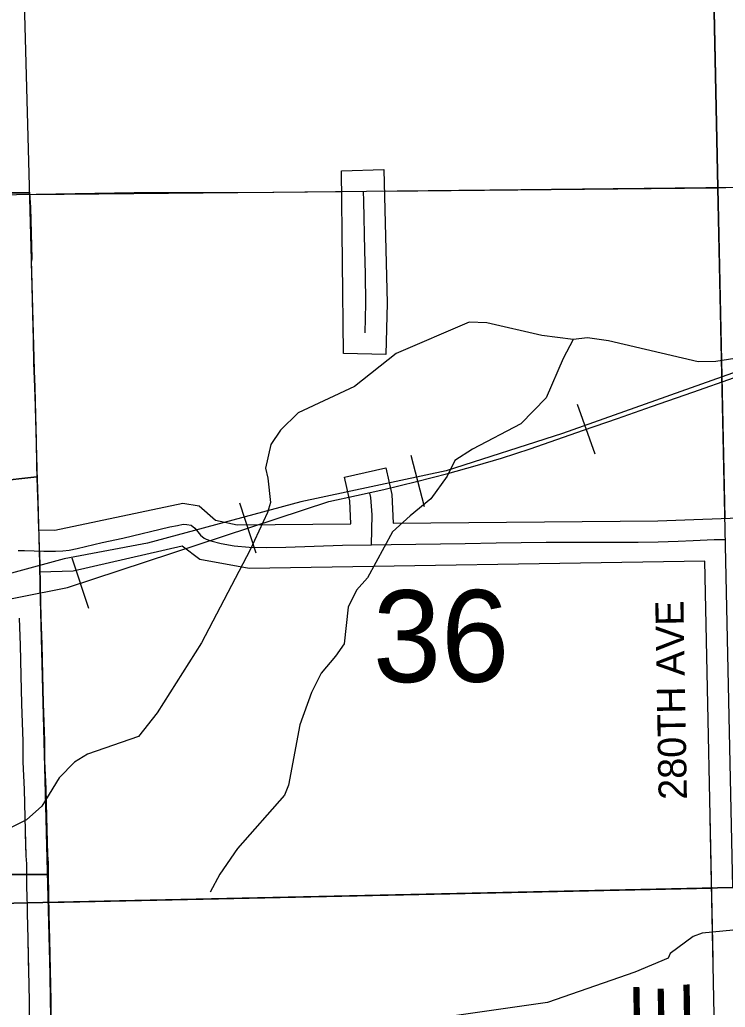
# Model space of a CAD drawing. Extents: x 10133 to 81668, y 7924 to 11018.
# Drawn here: x 11135.9 to 11285.8, y 9007.3 to 9217.2 of the extents above; entities that cross this region are included whole.
import ezdxf

# ---------------------------------------------------------------- set-up
doc = ezdxf.new("R2010")
doc.units = 0
for name, color, linetype in [('tdCoCityStreetMajor', 7, 'Continuous'), ('tdCoCityStreetMinor', 7, 'Continuous'), ('tdCoHydroRiver', 7, 'Continuous'), ('tdCoPriNonDiv', 7, 'Continuous'), ('tdCoRRCL', 7, 'Continuous'), ('tdCoRROwnerTxt', 7, 'Continuous'), ('tdCoSecRteBand', 7, 'Continuous'), ('tdCoShieldCoRteHrd', 7, 'Continuous'), ('tdCoShieldStRte', 7, 'Continuous'), ('tdCoStrucNonDivPri', 7, 'Continuous'), ('tdCoStrucSec', 7, 'Continuous'), ('tdCoSurfAsphalt', 7, 'Continuous'), ('tdCoSurfGravelUnbanded', 7, 'Continuous'), ('tdCoTwpNameTxt', 7, 'Continuous')]:
    doc.layers.add(name, color=color, linetype=linetype)

msp = doc.modelspace()

# ---------------------------------------------------------------- linework, layer by layer
at = {"layer": 'tdCoCityStreetMajor'}
for points in [[(11209.3, 9150.6), (11209.45, 9156.86), (11209.35, 9163.2), (11209.23, 9168.16), (11209.01, 9178.62), (11208.93, 9180.74)], [(11210.62, 9105.59), (11210.77, 9111.95), (11210.5, 9115.6), (11210.27, 9116.58)]]:
    msp.add_lwpolyline(points, dxfattribs=at)
at = {"layer": 'tdCoCityStreetMinor'}
msp.add_lwpolyline([(11135.49, 9104.34), (11136.86, 9104.35), (11140.98, 9104.2), (11143.44, 9104.2), (11145.05, 9104.3), (11146.33, 9104.4), (11148.05, 9104.75), (11153.36, 9106.03), (11157.75, 9107.01), (11167.78, 9109.38), (11169.36, 9109.7), (11170.62, 9109.92), (11171.41, 9109.87), (11172.27, 9109.73), (11173.09, 9109.13), (11173.73, 9108.3), (11174.29, 9107.63), (11175.06, 9106.99), (11175.5, 9106.74), (11176.51, 9106.42), (11178.68, 9105.86), (11181.47, 9105.36), (11184.65, 9105.04), (11188.38, 9105.02), (11192.42, 9105.09), (11204.48, 9105.49), (11210.62, 9105.59), (11214.84, 9105.66), (11230.54, 9105.86), (11237.15, 9106), (11247.78, 9106.15), (11255.58, 9106.15), (11267.34, 9106.15), (11271.58, 9106.18), (11275.82, 9106.32), (11279, 9106.5), (11283.47, 9106.67), (11285.91, 9106.73)], dxfattribs=at)
at = {"layer": 'tdCoHydroRiver'}
for points in [[(11253.47, 9149.25), (11246.83, 9150.09), (11235.18, 9152.73), (11231.39, 9152.91), (11215.87, 9146.25), (11206.99, 9139.24), (11195.01, 9133.59), (11191.28, 9129.97), (11189.2, 9126.86), (11188.1, 9121.87), (11188.61, 9119.75), (11189.17, 9114.55), (11188.5, 9112.4), (11184.84, 9104.53), (11174.52, 9084.7), (11165.06, 9069.86), (11161.12, 9064.82), (11150.29, 9061.09), (11147.47, 9059.38), (11144.22, 9056.01), (11140.53, 9050.03), (11137.26, 9047.13), (11129.51, 9043.22)], [(11292.36, 9145.88), (11283.86, 9144.55), (11280.07, 9144.49), (11261.05, 9148.9), (11256.54, 9149.54), (11253.47, 9149.25)], [(11253.47, 9149.25), (11251.41, 9145.19), (11247.76, 9136.84), (11242.41, 9131.31), (11232.08, 9125.92), (11228.33, 9123.49), (11226.73, 9120.15), (11223.26, 9115.36), (11218.82, 9111.73), (11215.09, 9108.35), (11209.8, 9098.55), (11207.48, 9095.91), (11205.65, 9092.33), (11204.83, 9084.5), (11202.98, 9081.86), (11199.96, 9078.26), (11197.9, 9074.2), (11195.41, 9067.29), (11193.02, 9054.46), (11192.11, 9052.32), (11182.12, 9041.02), (11178.42, 9035.51), (11176.35, 9031.69)], [(11344.52, 9029.3), (11332.9, 9030.29), (11329.6, 9029.53), (11322.5, 9029.17), (11318.94, 9029.58), (11313.04, 9028.3), (11292.23, 9026.77), (11287.55, 9023.61), (11280.93, 9023.02), (11279.04, 9022.28), (11274.13, 9018.65), (11274.05, 9018.47)], [(11287.54, 9023.61), (11280.92, 9023.02), (11279.04, 9022.28), (11274.13, 9018.65), (11273.67, 9017.69), (11266.62, 9014.73), (11248.02, 9008.26), (11227.7, 9005.32)]]:
    msp.add_lwpolyline(points, dxfattribs=at)
at = {"layer": 'tdCoPriNonDiv'}
for points in [[(11136.39, 9236.77), (11139.85, 9108.74), (11143.3, 9108.7)], [(11143.3, 9108.7), (11170.54, 9114.42), (11174.02, 9113.87), (11177.47, 9110.84), (11182.09, 9109.82), (11206.22, 9110.01), (11206.03, 9114.93), (11204.9, 9119.98), (11213.68, 9121.96), (11214.95, 9116.26), (11215.23, 9110.16), (11271.49, 9110.67), (11444.23, 9117.01), (11445.46, 9211.77), (11445.79, 9217.23)], [(11213.69, 9146), (11204.7, 9146.21), (11204.28, 9185.07), (11213.27, 9185.39), (11213.95, 9156.93), (11213.69, 9146)], [(11283.23, 9017.59), (11281.5, 9102.09), (11184.62, 9100.54), (11174.14, 9102.45), (11170.36, 9105.31), (11147.21, 9099.99), (11140.11, 9099.73), (11140.14, 9096.7), (11142.28, 9014.33)], [(11144.18, 8888.05), (11285.56, 8897.14), (11285.05, 8928.68), (11282.62, 9047.57)], [(11141.5, 9044.31), (11142.42, 9008.73), (11144.18, 8888.05)]]:
    msp.add_lwpolyline(points, dxfattribs=at)
at = {"layer": 'tdCoRRCL'}
for p, q in [((11258.16, 9124.81), (11254.45, 9135.43)), ((11221.88, 9113.64), (11219.09, 9124.54)), ((11186.14, 9103.77), (11182.62, 9114.45)), ((11150.52, 9092.04), (11147, 9102.72))]:
    msp.add_line(p, q, dxfattribs=at)
for points in [[(11383.11, 9177.72), (11374.43, 9174.35), (11360.55, 9167.76), (11338.88, 9160.33), (11251.25, 9129.22), (11226.5, 9121.28), (11195.58, 9114.67), (11163.03, 9105.91), (11145.32, 9102.57), (11125.98, 9097.32), (11109.94, 9093.06), (11085.46, 9083.46), (11066.85, 9076.56), (10954.88, 9032.59)], [(11124.89, 9092.32), (11146.01, 9096.47), (11201.59, 9114.78), (11207.43, 9116.04), (11213.27, 9117.29), (11216.75, 9118.16), (11220.23, 9119.02), (11226.83, 9120.72), (11232.65, 9122.37), (11238.24, 9123.98), (11244.33, 9125.98), (11250.03, 9127.95), (11255.73, 9129.92), (11262.93, 9132.43), (11270.13, 9134.95), (11278.95, 9138.04), (11287.78, 9141.12)]]:
    msp.add_lwpolyline(points, dxfattribs=at)
at = {"layer": 'tdCoSecRteBand'}
for points in [[(11137.81, 9014.23), (11137.67, 9021.57), (11137.59, 9024.74), (11137.54, 9026.95), (11137.5, 9028.68), (11137.44, 9030.79), (11137.37, 9032.84), (11137.34, 9037.75), (11137.22, 9039.42), (11137, 9047.64), (11136.85, 9053.53), (11136.61, 9059.45), (11136.58, 9063.72), (11136.33, 9071.78), (11136.19, 9077.8), (11136.01, 9084.23), (11135.84, 9089.95)], [(11139.8, 8879.28), (11139.75, 8883.2), (11139.67, 8889.05), (11139.41, 8905.29), (11139, 8929.96), (11138.85, 8947.61), (11138.63, 8957.74), (11138.44, 8972.39), (11138.3, 8982.6), (11138, 8999.95), (11137.93, 9008.64), (11137.67, 9021.57), (11137.59, 9024.74), (11137.54, 9026.95), (11137.5, 9028.68), (11137.44, 9030.79), (11137.37, 9032.84), (11137.34, 9037.75), (11137.22, 9039.43), (11137.09, 9044.21)]]:
    msp.add_lwpolyline(points, dxfattribs=at)
at = {"layer": 'tdCoShieldCoRteHrd'}
for points in [[(11142.01, 9029.52), (11282.99, 9032.59)], [(11142.01, 9029.52), (11283, 9032.59)]]:
    msp.add_lwpolyline(points, dxfattribs=at)
at = {"layer": 'tdCoStrucNonDivPri'}
for points in [[(11281.2, 9328.24), (11284.23, 9181.46)], [(11284.23, 9181.46), (11445.26, 9188.14)], [(11213.39, 9180.78), (11284.23, 9181.46)], [(11284.23, 9181.46), (11285.76, 9111.23)], [(11137.91, 9180.05), (11204.39, 9180.69)], [(11142.01, 9029.52), (11282.99, 9032.59)], [(11142.01, 9029.52), (11283, 9032.59)]]:
    msp.add_lwpolyline(points, dxfattribs=at)
at = {"layer": 'tdCoStrucSec'}
msp.add_lwpolyline([(10954.88, 9175.44), (11041.44, 9177.24), (11055.35, 9177.93), (11080.24, 9178.84), (11116.14, 9179.9), (11130.94, 9179.97), (11160.16, 9180.44), (11189.9, 9180.57), (11314.49, 9181.85), (11344.65, 9183.03), (11380.85, 9184.91), (11405.4, 9186.53), (11423.46, 9187.1), (11448.12, 9188.29), (11485.13, 9189.73)], dxfattribs=at)
at = {"layer": 'tdCoSurfAsphalt'}
for p, q in [((11137.88, 9180.38), (11128.88, 9180.38)), ((11137.9, 9180.39), (11128.9, 9180.39))]:
    msp.add_line(p, q, dxfattribs=at)
for points in [[(11128.9, 9180.39), (11137.9, 9180.39), (11138.16, 9177.26), (11138.4, 9166.34), (11138.3, 9165.63), (11138.44, 9160.59), (11138.59, 9154.57), (11138.74, 9149.18), (11138.83, 9144.24), (11139.05, 9139.1), (11139.23, 9133.04), (11139.35, 9127.74), (11139.45, 9122.41), (11139.52, 9119.99), (11130.55, 9119.04)], [(11137.88, 9180.38), (11138.14, 9177.25), (11138.37, 9166.33), (11138.28, 9165.62), (11138.42, 9160.58), (11138.56, 9154.56), (11138.71, 9149.17), (11138.81, 9144.23), (11139.03, 9139.09), (11139.2, 9133.03), (11139.33, 9127.73), (11139.43, 9122.39), (11139.57, 9117.57), (11139.75, 9112.46), (11139.89, 9107.04), (11140.09, 9101.5), (11140.14, 9096.7), (11140.34, 9090.09), (11140.51, 9084.36), (11140.68, 9077.91), (11140.83, 9071.9), (11141.08, 9063.8), (11141.1, 9059.56), (11141.35, 9053.68), (11141.5, 9047.75), (11141.72, 9039.65), (11141.84, 9037.92), (11141.87, 9032.93), (11141.94, 9030.93), (11142.04, 9027.06), (11142.16, 9021.67), (11142.31, 9014.32)], [(11137.9, 9180.39), (11138.16, 9177.26), (11138.4, 9166.34), (11138.3, 9165.63), (11138.44, 9160.59), (11138.59, 9154.57), (11138.74, 9149.18), (11138.83, 9144.24), (11139.05, 9139.1), (11139.23, 9133.04), (11139.35, 9127.74), (11139.45, 9122.41), (11139.6, 9117.58), (11139.77, 9112.47), (11139.92, 9107.05), (11140.12, 9101.51), (11140.17, 9096.71), (11140.36, 9090.1), (11140.54, 9084.37), (11140.71, 9077.92), (11140.86, 9071.92), (11141.1, 9063.81), (11141.13, 9059.57), (11141.37, 9053.69), (11141.52, 9047.77), (11141.74, 9039.66), (11141.87, 9037.94), (11141.89, 9032.94), (11141.97, 9030.94), (11142.06, 9027.07), (11142.19, 9021.68), (11142.34, 9014.33)], [(11130.55, 9119.04), (11139.52, 9119.99), (11139.6, 9117.58), (11139.77, 9112.47), (11139.92, 9107.05), (11140.12, 9101.51), (11140.17, 9096.71), (11140.36, 9090.1), (11140.54, 9084.37), (11140.71, 9077.92), (11140.86, 9071.92), (11141.1, 9063.81), (11141.13, 9059.57), (11141.37, 9053.69), (11141.52, 9047.77), (11141.61, 9044.34), (11141.74, 9039.66), (11141.74, 9039.66), (11141.87, 9037.94), (11141.88, 9035.44), (11132.88, 9035.44)], [(11141.59, 9044.33), (11141.72, 9039.65), (11141.84, 9037.93), (11141.87, 9032.93), (11141.94, 9030.93), (11142.04, 9027.06), (11142.16, 9021.67), (11142.43, 9008.7), (11142.5, 9000), (11142.8, 8982.67), (11142.94, 8972.45), (11143.13, 8957.82), (11143.35, 8947.67), (11143.5, 8930.02), (11143.91, 8905.36), (11144.17, 8889.12), (11144.3, 8879.35)], [(11141.61, 9044.34), (11141.74, 9039.66), (11141.87, 9037.94), (11141.89, 9032.95), (11141.97, 9030.95), (11142.06, 9027.07), (11142.19, 9021.68), (11142.45, 9008.72), (11142.52, 9000.02), (11142.82, 8982.68), (11142.97, 8972.46), (11143.15, 8957.83), (11143.38, 8947.69), (11143.52, 8930.03), (11143.93, 8905.37), (11144.19, 8889.13), (11144.32, 8879.36)]]:
    msp.add_lwpolyline(points, dxfattribs=at)
msp.add_lwpolyline([(11132.89, 9033.19), (11132.88, 9035.44), (11141.88, 9035.44), (11146.71, 8738.97), (11294.17, 8746), (11308.79, 8746.04), (11334.35, 8746.15), (11366.91, 8746.3), (11391.58, 8746.26), (11425.21, 8746.56), (11449.9, 8746.78), (11483.73, 8746.82), (11483.73, 8737.82), (11483.67, 8737.82), (11449.95, 8737.78), (11425.29, 8737.56), (11391.61, 8737.26), (11366.93, 8737.3), (11334.39, 8737.15), (11308.82, 8737.04), (11294.37, 8737), (11219.06, 8732.98), (11137.76, 8729.58)], close=True, dxfattribs=at)
at = {"layer": 'tdCoSurfGravelUnbanded'}
msp.add_lwpolyline([(11281.2, 9328.24), (11284.23, 9181.46), (11285.76, 9111.23)], dxfattribs=at)
at = {"layer": 'tdCoTwpNameTxt'}
for points in [[(12204.65, 9594.91), (12205.81, 9506.76), (12207.26, 9355.85), (12207.65, 9199.23), (12206.71, 9053.29), (12058.44, 9052.45), (12055.44, 9052.43), (11906.7, 9050.03), (11903.62, 9049.96), (11751.72, 9046.27), (11602.3, 9041.92), (11599.58, 9041.89), (11448.66, 9038.75), (11287.47, 9032.68), (11137.48, 9029.42), (10987.91, 9025.85), (10954.88, 9025.06)], [(11287.47, 9032.68), (11284.23, 9181.46), (11281.14, 9331.19), (11278.77, 9457.01), (11277.18, 9480.27), (11277.53, 9527.34), (11276.22, 9594.91)], [(10954.88, 9025.06), (10987.91, 9025.85), (11137.48, 9029.42), (11287.46, 9032.68), (11448.65, 9038.75), (11599.58, 9041.89), (11602.29, 9041.92), (11751.71, 9046.27), (11903.62, 9049.96), (11906.69, 9050.03), (12055.44, 9052.43), (12058.43, 9052.45), (12206.7, 9053.29), (12354.1, 9050.96), (12408.9, 9050.4)]]:
    msp.add_lwpolyline(points, dxfattribs=at)

# ---------------------------------------------------------------- texts
at = {"layer": 'tdCoRROwnerTxt'}
msp.add_text('36', height=19.5, rotation=0.2267, dxfattribs=at).set_placement((11210.95, 9076.36))
at = {"layer": 'tdCoShieldStRte'}
for s, height, p in [('280TH AVE', 6, (11277.69, 9051.41)), ('GINKGO AVE', 12, (11280.01, 8912.04))]:
    msp.add_text(s, height=height, rotation=91, dxfattribs=at).set_placement(p)

doc.saveas('drawing.dxf')
